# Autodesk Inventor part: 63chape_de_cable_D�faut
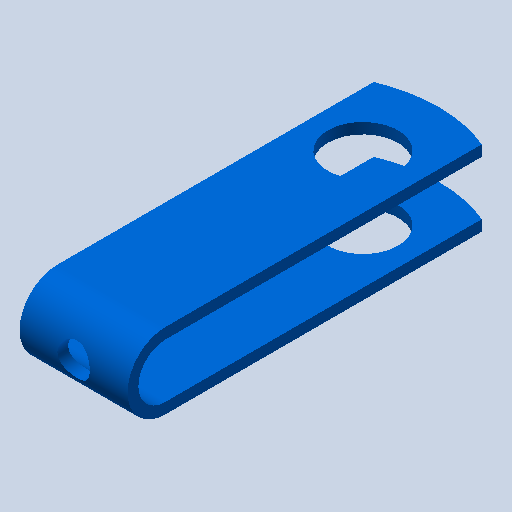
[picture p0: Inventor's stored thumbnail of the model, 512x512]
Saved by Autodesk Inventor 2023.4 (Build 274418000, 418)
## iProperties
Created: 2011-01
Part Number: 63chape_de_cable_D�faut
Document SubType Name: Modeling
Designer: eric
Density: 1 g/cm^3
Mass: 0.619745 g
Surface Area: 14.4697 cm^2
Volume: 0.619745 cm^3
Material: Générique
Appearance: 0,128,255_1
Author: eric
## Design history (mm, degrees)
feature "Base1"
node "Corps solides"
node "Corps surfaciques"
node "Solide1"
